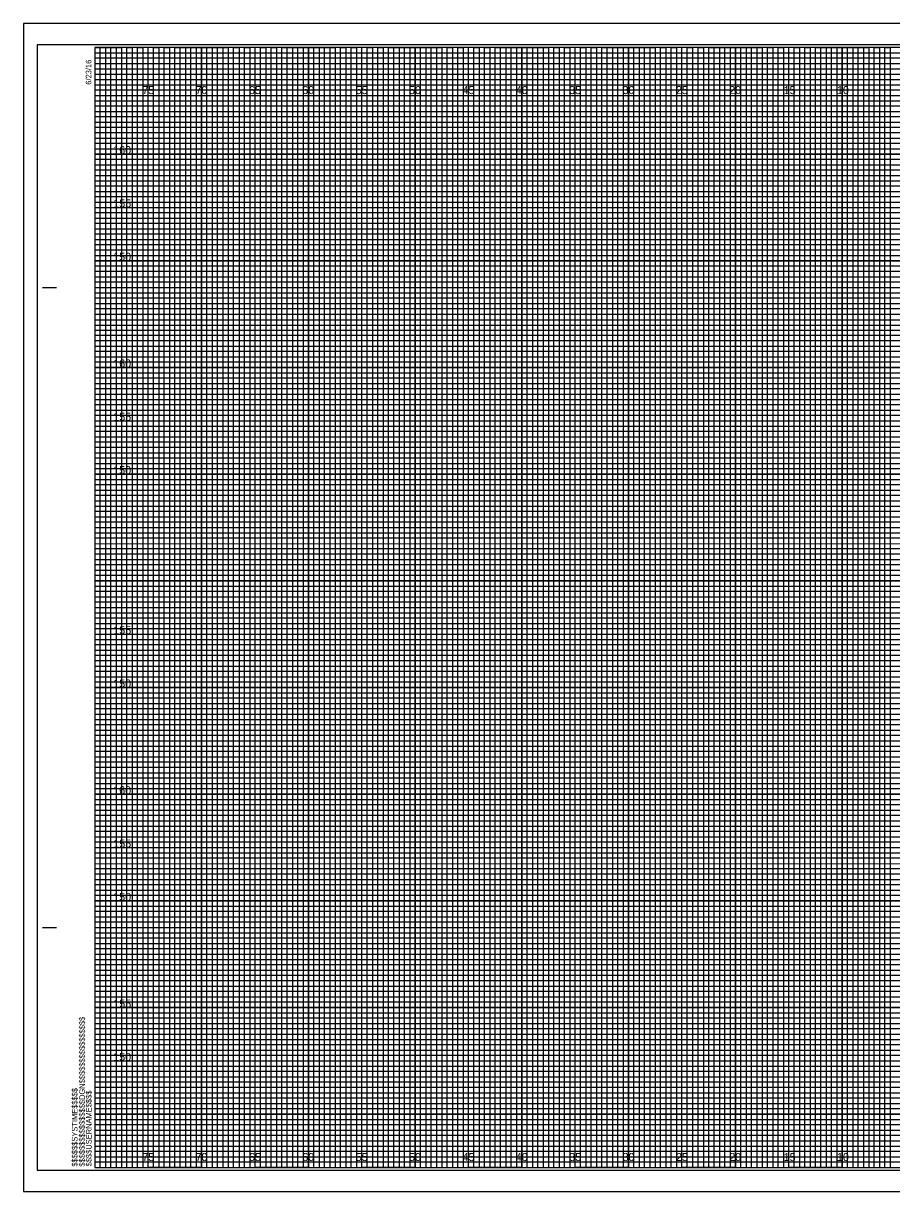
# Model space of a CAD drawing. Extents: x -7 to 162, y -2 to 107.
# Drawn here: x -6.7 to 74.6, y -2.3 to 107.3 of the extents above; entities that cross this region are included whole.
import ezdxf

# ---------------------------------------------------------------- set-up
doc = ezdxf.new("R2010")
doc.units = 0
for name, color, linetype in [('Exist CMT Pavement', 7, 'Continuous'), ('Prop CMT Pvmt Course 1 Wedge', 7, 'Continuous'), ('Prop CMT Pvmt Course 2 Wedge', 7, 'Continuous'), ('Prop CMT Pvmt Course 3 Wedge', 7, 'Continuous'), ('Prop CMT Pvmt Wedge Surface 1', 7, 'Continuous'), ('Prop CMT Pvmt Wedge Surface 2', 7, 'Continuous'), ('Prop CMT Shear Line', 7, 'Continuous'), ('Prop XS Elevation Labels', 7, 'Continuous'), ('Prop XS Label Text', 7, 'Continuous'), ('Scratch_Level_1', 7, 'Continuous'), ('Sheet Cutting Line CELL', 7, 'Continuous')]:
    doc.layers.add(name, color=color, linetype=linetype)

msp = doc.modelspace()

# ---------------------------------------------------------------- linework, layer by layer
at = {"layer": 'Exist CMT Pavement'}
for p, q in [((0, 104.5), (130, 104.5)), ((130, 103.99), (0, 103.99)), ((0, 103.99), (0, 103.5)), ((0, 103.5), (130, 103.5)), ((130, 102.95), (0, 102.95)), ((0, 102.95), (0, 102)), ((0, 102), (160, 102))]:
    msp.add_line(p, q, dxfattribs=at)
for points in [[(0, 101.5), (135, 101.5), (160, 101.5), (160, 101), (0, 101)], [(0, 100.5), (160, 100.5), (160, 99.5), (0, 99.5)], [(0, 99), (160, 99), (160, 98.5), (0, 98.49)], [(0, 98), (160, 98), (160, 97), (0, 97)], [(0, 96.5), (160, 96.5), (160, 96), (0, 96)], [(0, 95.5), (160, 95.5), (160, 94.5), (0, 94.5)], [(0, 94), (160, 94), (160, 93.5), (0, 93.5)], [(0, 93), (160, 93), (160, 92), (0, 92)], [(0, 91.5), (160, 91.5), (160, 91), (0, 91)], [(0, 90.5), (160, 90.5), (160, 89.5), (0, 89.5)], [(0, 89), (160, 89), (160, 88.5), (0, 88.5)], [(0, 88), (160, 88), (160, 86.98), (160, 86.5), (160, 86), (0, 86)], [(0, 87), (160, 87), (160, 86.5), (0, 86.5)], [(0, 85.5), (160, 85.5), (160, 84.5), (0, 84.52)], [(0, 84.52), (160, 84.5), (160, 84), (0, 84)], [(0, 83.5), (160, 83.5), (160, 83), (0, 83)], [(0, 82), (160, 82), (160, 81.5), (0, 81.5)], [(0, 81), (160, 81), (160, 80.5), (0, 80.5)], [(-0.04, 79.45), (160, 79.45), (160, 78.94), (-0.04, 78.94)], [(0, 78.5), (160, 78.5), (160, 78), (0, 78)], [(0, 77), (160, 77), (160, 76.5), (0, 76.5)], [(0, 76), (160, 76), (160, 75.5), (0, 75.5)], [(0, 74.5), (160, 74.5), (160, 74), (0, 74)], [(0, 73.5), (160, 73.5), (160, 73), (0, 73)], [(0, 72), (160, 72), (160, 71.5), (0, 71.5)], [(0, 71), (160, 71), (160, 70.5), (0, 70.5)], [(0, 69.5), (160, 69.5), (160, 68.99), (0, 69)], [(0, 68.5), (160, 68.5), (160, 68), (0, 68)], [(0, 67), (160, 67), (160, 66.5), (0, 66.5)], [(0, 66), (160, 66), (160, 65.5), (0, 65.5)], [(0, 64.5), (160, 64.5), (160, 64), (0, 64)], [(0, 63.5), (160, 63.5), (160, 63), (0, 63)], [(0, 62), (160, 62), (160, 61.5), (0, 61.5)], [(0, 61), (160, 61), (160, 60.5), (0, 60.5)], [(0, 59.5), (160, 59.5), (160, 59), (0, 59)], [(0, 58.5), (160.03, 58.45), (160, 58), (0, 58)], [(0, 57), (160, 57), (160, 56.5), (0, 56.5)], [(0, 56), (160, 56), (160, 55.5), (0, 55.5)], [(0, 54.5), (160, 54.5), (160, 54), (0, 54)], [(0, 53.5), (160, 53.5), (160, 53), (0, 53)], [(0, 52), (160, 52), (160, 51.5), (0, 51.5)], [(0, 51), (160, 51), (160, 50.5), (0, 50.5)], [(0, 49.5), (160, 49.5), (160, 49), (0, 49)], [(0, 48.5), (160, 48.5), (160, 48), (0, 48)], [(0, 47), (160, 47), (160, 46.5), (0, 46.5)], [(0, 46), (160, 46), (160, 45.5), (0, 45.5)], [(0, 44.5), (160, 44.5), (160, 44), (0, 44)], [(0, 43.5), (160, 43.5), (160, 43), (0, 43)], [(0, 42), (160, 42), (160, 41.5), (0, 41.5)], [(0, 41), (160, 41), (160, 40.5), (0, 40.5)], [(0, 39.5), (160, 39.5), (160, 38.99), (0, 39)], [(0, 38.5), (160, 38.5), (160, 38), (0, 38)], [(0, 37), (160, 37), (160, 36.5), (0, 36.5)], [(0, 36), (160, 36), (160, 35.5), (0, 35.5)], [(0, 34.5), (160, 34.5), (160, 34), (0, 34)], [(0, 33.5), (160, 33.5), (160, 33), (0, 33)], [(0, 32), (160, 32), (160, 31.5), (0, 31.5)], [(0, 31), (160, 31), (160, 30.5), (0, 30.5)], [(0, 29.5), (160, 29.5), (160, 29), (0, 29)], [(0, 28.5), (160.03, 28.46), (160, 28), (0, 28)], [(0, 27), (160, 27), (160, 26.5), (0, 26.5)], [(0, 26), (160, 26), (160, 25.5), (0, 25.5)], [(0, 24.5), (160, 24.5), (160, 24), (0, 24)], [(0, 23.5), (160, 23.5), (160, 23), (0, 23)], [(0, 22), (160, 22), (160, 21.5), (0, 21.5)], [(0, 21), (160, 21), (160, 20.5), (0, 20.5)], [(0, 19.5), (160, 19.5), (160, 19), (0, 19)], [(0, 18.5), (160, 18.5), (160, 18), (0, 18)], [(0, 17), (160, 17), (160, 16.5), (0, 16.5)], [(0, 16), (160, 16), (160, 15.5), (0, 15.5)], [(0, 14.5), (160, 14.5), (160, 14), (0, 14)], [(0, 13.5), (160, 13.5), (160, 13), (0, 13)], [(0, 12), (160, 12), (160, 11.5), (0, 11.5)], [(0, 11), (160, 11), (160, 10.5), (0, 10.5)], [(0, 9.5), (160, 9.5), (160, 9), (0, 9)], [(0, 8.5), (160, 8.5), (160, 8), (0, 8)], [(0, 7), (160, 7), (160, 6.5), (0, 6.5)], [(0, 6), (160, 6), (160, 5.5), (0, 5.5)], [(0, 4.5), (160, 4.5), (160, 4), (0, 4)], [(0, 3.5), (160, 3.5), (160, 3), (0, 3)], [(0, 2), (160, 2), (160, 1.5), (0, 1.5)], [(0, 1), (160, 1), (160, 0.5), (0, 0.5)]]:
    msp.add_lwpolyline(points, dxfattribs=at)
at = {"layer": 'Prop CMT Pvmt Course 2 Wedge'}
for p, q in [((5, 105), (0, 105)), ((5, 0), (5, 105)), ((15, 105), (10, 105)), ((10, 105), (10, 0)), ((15, 0), (15, 105)), ((25, 105), (20, 105)), ((20, 105), (20, 0)), ((25, 0), (25, 105)), ((35, 105), (30, 105)), ((30, 105), (30, 0)), ((35, 0), (35, 105)), ((45, 105), (40, 105)), ((40, 105), (40, 0)), ((45, 0), (45, 105)), ((55, 105), (50, 105)), ((50, 105), (50, 0)), ((55, 0), (55, 105)), ((65, 105), (60, 105)), ((60, 105), (60, 0)), ((65, 0), (65, 105)), ((75, 105), (70, 105)), ((70, 105), (70, 0)), ((10, 0), (5, 0)), ((20, 0), (15, 0)), ((30, 0), (25, 0)), ((40, 0), (35, 0)), ((50, 0), (45, 0)), ((60, 0), (55, 0)), ((70, 0), (65, 0))]:
    msp.add_line(p, q, dxfattribs=at)
for points in [[(0, 100), (160, 100), (160, 95), (0, 95)], [(0, 90), (160, 90), (160, 85), (0, 85)], [(0, 80), (160, 80), (160, 75), (0, 75)], [(0, 70), (160, 70), (160, 65), (0, 65)], [(0, 60), (160, 60), (160, 55), (0, 55)], [(0, 50), (160, 50), (160, 45), (0, 45)], [(0, 40), (160, 40), (160, 35), (0, 35)], [(0, 30), (160, 30), (160, 25), (0, 25)], [(0, 20), (160, 20), (160, 15), (0, 15)], [(0, 10), (160, 10), (160, 5), (0, 5)]]:
    msp.add_lwpolyline(points, dxfattribs=at)
at = {"layer": 'Prop CMT Pvmt Course 3 Wedge'}
for points in [[(0, 105), (2.5, 105), (2.5, 0), (7.5, 0), (7.5, 105), (12.5, 105), (12.5, 0), (17.5, 0), (17.5, 105), (22.5, 105), (22.5, 0), (27.5, 0), (27.5, 105), (32.5, 105), (32.5, 0), (37.5, 0), (37.5, 105), (42.5, 105), (42.5, 0), (47.5, 0), (47.5, 105), (52.5, 105), (52.5, 0), (57.5, 0), (57.5, 105), (62.5, 105), (62.5, 0), (67.5, 0), (67.5, 105), (72.5, 105), (72.5, 0), (77.5, 0)], [(0, 102.5), (137.5, 102.5)], [(0, 92.5), (160, 92.5), (160, 97.5), (0, 97.5)], [(0, 82.5), (160, 82.5), (160, 87.5), (0, 87.5)], [(0, 72.5), (160, 72.5), (160, 77.5), (0, 77.5)], [(0, 62.5), (160, 62.5), (160, 67.5), (0, 67.5)], [(0, 52.5), (160, 52.5), (160, 57.5), (0, 57.5)], [(0, 42.5), (160, 42.5), (160, 47.5), (0, 47.5)], [(0, 32.5), (160, 32.5), (160, 37.5), (0, 37.5)], [(0, 22.5), (160, 22.5), (160, 27.5), (0, 27.5)], [(0, 12.5), (160, 12.5), (160, 17.5), (0, 17.5)], [(0, 2.5), (160, 2.5), (160, 7.5), (0, 7.5)]]:
    msp.add_lwpolyline(points, dxfattribs=at)
at = {"layer": 'Prop CMT Pvmt Wedge Surface 1'}
for p, q in [((-4.9, 82.5), (-3.65, 82.5)), ((-4.85, 82.5), (-3.6, 82.5)), ((-4.9, 22.5), (-3.65, 22.5)), ((-4.85, 22.5), (-3.6, 22.5)), ((0, 0), (0, 0)), ((0, 0), (0, 0)), ((0, 0), (0, 0)), ((0, 0), (0, 0)), ((0, 0), (0, 0)), ((0, 0), (0, 0)), ((0, 0), (0, 0))]:
    msp.add_line(p, q, dxfattribs=at)
msp.add_lwpolyline([(160, 105), (0, 105), (0, 0), (160, 0)], close=True, dxfattribs=at)
at = {"layer": 'Prop CMT Pvmt Wedge Surface 2'}
for points in [[(0, 0), (0.5, 0), (0.5, 105), (1, 105), (1, 0)], [(1, 0), (1.5, 0), (1.5, 105), (2, 105), (2, 0)], [(2.5, 0), (3, 0), (3, 105), (3.5, 105), (3.5, 0)], [(3.5, 0), (4, 0), (4, 105), (4.5, 105), (4.5, 0)], [(5, 0), (5.5, 0), (5.5, 105), (6, 105), (6, 0)], [(6, 0), (6.5, 0), (6.5, 105), (7, 105), (7, 0)], [(7.5, 0), (8, 0), (8, 105), (8.5, 105), (8.5, 0)], [(8.5, 0), (9, 0), (9, 105), (9.5, 105), (9.5, 0)], [(10, 0), (10.5, 0), (10.5, 105), (11, 105), (11, 0)], [(11, 0), (11.5, 0), (11.5, 105), (12, 105), (12, 0)], [(12.5, 0), (13, 0), (13, 105), (13.5, 105), (13.5, 0)], [(13.5, 0), (14, 0), (14, 105), (14.5, 105), (14.5, 0)], [(15, 0), (15.5, 0), (15.5, 105), (16, 105), (16, 0)], [(16, 0), (16.5, 0), (16.5, 105), (17, 105), (17, 0)], [(17.5, 0), (18, 0), (18, 105), (18.5, 105), (18.5, 0)], [(18.5, 0), (19, 0), (19, 105), (19.5, 105), (19.5, 0)], [(20, 0), (20.5, 0), (20.5, 105), (21, 105), (21, 0)], [(21, 0), (21.5, 0), (21.5, 105), (22, 105), (22, 0)], [(22.5, 0), (23, 0), (23, 105), (23.5, 105), (23.5, 0)], [(23.5, 0), (24, 0), (24, 105), (24.5, 105), (24.5, 0)], [(25, 0), (25.5, 0), (25.5, 105), (26, 105), (26, 0)], [(26, 0), (26.5, 0), (26.5, 105), (27, 105), (27, 0)], [(27.5, 0), (28, 0), (28, 105), (28.5, 105), (28.5, 0)], [(28.5, 0), (29, 0), (29, 105), (29.5, 105), (29.5, 0)], [(30, 0), (30.5, 0), (30.5, 105), (31, 105), (31, 0)], [(31, 0), (31.5, 0), (31.5, 105), (32, 105), (32, 0)], [(32.5, 0), (33, 0), (33, 105), (33.5, 105), (33.5, 0)], [(33.5, 0), (34, 0), (34, 105), (34.5, 105), (34.5, 0)], [(35, 0), (35.5, 0), (35.5, 105), (36, 105), (36, 0)], [(36, 0), (36.5, 0), (36.5, 105), (37, 105), (37, 0)], [(37.5, 0), (38, 0), (38, 105), (38.5, 105), (38.5, 0)], [(38.5, 0), (39, 0), (39, 105), (39.5, 105), (39.5, 0)], [(40, 0), (40.5, 0), (40.5, 105), (41, 105), (41, 0)], [(41, 0), (41.5, 0), (41.5, 105), (42, 105), (42, 0)], [(42.5, 0), (43, 0), (43, 105), (43.5, 105), (43.5, 0)], [(43.5, 0), (44, 0), (44, 105), (44.5, 105), (44.5, 0)], [(45, 0), (45.5, 0), (45.5, 105), (46, 105), (46, 0)], [(46, 0), (46.5, 0), (46.5, 105), (47, 105), (47, 0)], [(47.5, 0), (48, 0), (48, 105), (48.5, 105), (48.5, 0)], [(48.5, 0), (49, 0), (49, 105), (49.5, 105), (49.5, 0)], [(50, 0), (50.5, 0), (50.5, 105), (51, 105), (51, 0)], [(51, 0), (51.5, 0), (51.5, 105), (52, 105), (52, 0)], [(52.5, 0), (53, 0), (53, 105), (53.5, 105), (53.5, 0)], [(53.5, 0), (54, 0), (54, 105), (54.5, 105), (54.5, 0)], [(55, 0), (55.5, 0), (55.5, 105), (56, 105), (56, 0)], [(56, 0), (56.5, 0), (56.5, 105), (57, 105), (57, 0)], [(57.5, 0), (58, 0), (58, 105), (58.5, 105), (58.5, 0)], [(58.5, 0), (59, 0), (59, 105), (59.5, 105), (59.5, 0)], [(60, 0), (60.5, 0), (60.5, 105), (61, 105), (61, 0)], [(61, 0), (61.5, 0), (61.5, 105), (62, 105), (62, 0)], [(62.5, 0), (63, 0), (63, 105), (63.5, 105), (63.5, 0)], [(63.5, 0), (64, 0), (64, 105), (64.5, 105), (64.5, 0)], [(65, 0), (65.5, 0), (65.5, 105), (66, 105), (66, 0)], [(66, 0), (66.5, 0), (66.5, 105), (67, 105), (67, 0)], [(67.5, 0), (68, 0), (68, 105), (68.5, 105), (68.5, 0)], [(68.5, 0), (69, 0), (69, 105), (69.5, 105), (69.5, 0)], [(70, 0), (70.5, 0), (70.5, 105), (71, 105), (71, 0)], [(71, 0), (71.5, 0), (71.5, 105), (72, 105), (72, 0)], [(72.5, 0), (73, 0), (73, 105), (73.5, 105), (73.5, 0)], [(73.5, 0), (74, 0), (74, 105), (74.5, 105), (74.5, 0)]]:
    msp.add_lwpolyline(points, dxfattribs=at)
at = {"layer": 'Prop CMT Shear Line'}
msp.add_lwpolyline([(-5.4, -0.25), (161.2, -0.25), (161.2, 105.25), (-5.4, 105.25)], close=True, dxfattribs=at)
at = {"layer": 'Prop XS Label Text'}
msp.add_lwpolyline([(-6.7, -2.25), (161.65, -2.25), (161.65, 107.25), (-6.7, 107.25)], close=True, dxfattribs=at)
at = {"layer": 'Scratch_Level_1'}
for p, q in [((5, 0), (5, 105)), ((10, 0), (10, 105)), ((15, 0), (15, 105)), ((20, 0), (20, 105)), ((25, 0), (25, 105)), ((30, 0), (30, 105)), ((35, 0), (35, 105)), ((40, 0), (40, 105)), ((45, 0), (45, 105)), ((50, 0), (50, 105)), ((55, 0), (55, 105)), ((60, 0), (60, 105)), ((65, 0), (65, 105)), ((70, 0), (70, 105)), ((0, 100), (160, 100)), ((0, 95), (160, 95)), ((0, 90), (160, 90)), ((0, 85), (160, 85)), ((0, 80), (160, 80)), ((0, 75), (160, 75)), ((0, 70), (160, 70)), ((0, 65), (160, 65)), ((0, 60), (160, 60)), ((0, 55), (160, 55)), ((0, 50), (160, 50)), ((0, 45), (160, 45)), ((0, 40), (160, 40)), ((0, 35), (160, 35)), ((0, 30), (160, 30)), ((0, 25), (160, 25)), ((0, 20), (160, 20)), ((0, 15), (160, 15)), ((0, 10), (160, 10)), ((0, 5), (160, 5))]:
    msp.add_line(p, q, dxfattribs=at)
at = {"layer": 'Sheet Cutting Line CELL'}
for p, q in [((161.65, 107.25), (-6.7, 107.25)), ((-6.7, 107.25), (-6.7, -2.25)), ((-6.7, -2.25), (161.65, -2.25))]:
    msp.add_line(p, q, dxfattribs=at)

# ---------------------------------------------------------------- texts
at = {"layer": 'Prop CMT Pvmt Course 1 Wedge'}
for s, p in [('75', (4.44, 100.62)), ('70', (9.43, 100.62)), ('65', (14.44, 100.62)), ('60', (19.43, 100.62)), ('55', (24.44, 100.62)), ('50', (29.43, 100.62)), ('45', (34.44, 100.62)), ('40', (39.43, 100.62)), ('35', (44.44, 100.62)), ('30', (49.43, 100.62)), ('25', (54.44, 100.62)), ('20', (59.43, 100.62)), ('15', (64.53, 100.62)), ('10', (69.52, 100.62)), ('75', (4.44, 0.62)), ('70', (9.43, 0.62)), ('65', (14.44, 0.62)), ('60', (19.43, 0.62)), ('55', (24.44, 0.62)), ('50', (29.43, 0.62)), ('45', (34.44, 0.62)), ('40', (39.43, 0.62)), ('35', (44.44, 0.62)), ('30', (49.43, 0.62)), ('25', (54.44, 0.62)), ('20', (59.43, 0.62)), ('15', (64.53, 0.62)), ('10', (69.52, 0.62))]:
    msp.add_text(s, height=0.75, dxfattribs=at).set_placement(p)
at = {"layer": 'Prop CMT Pvmt Wedge Surface 1'}
for s, p in [('6/23/16', (-0.33, 101.5)), ('$$$$$$$$$$$$$$$$DGN$$$$$$$$$$$$$$$$', (-0.94, 0.09)), ('$$$$$$SYSTIME$$$$$', (-1.63, 0.09)), ('$$$$USERNAME$$$$', (-0.31, 0.12))]:
    msp.add_text(s, height=0.525, rotation=90, dxfattribs=at).set_placement(p)
at = {"layer": 'Prop XS Elevation Labels'}
for s, p in [('160', (1.72, 95)), ('155', (1.73, 90)), ('150', (1.72, 85)), ('160', (1.72, 75)), ('155', (1.73, 70)), ('150', (1.72, 65)), ('155', (1.73, 50)), ('150', (1.72, 45)), ('160', (1.72, 35)), ('155', (1.73, 30)), ('150', (1.72, 25)), ('155', (1.73, 15)), ('150', (1.72, 10))]:
    msp.add_text(s, height=0.75, dxfattribs=at).set_placement(p)

doc.saveas('drawing.dxf')
